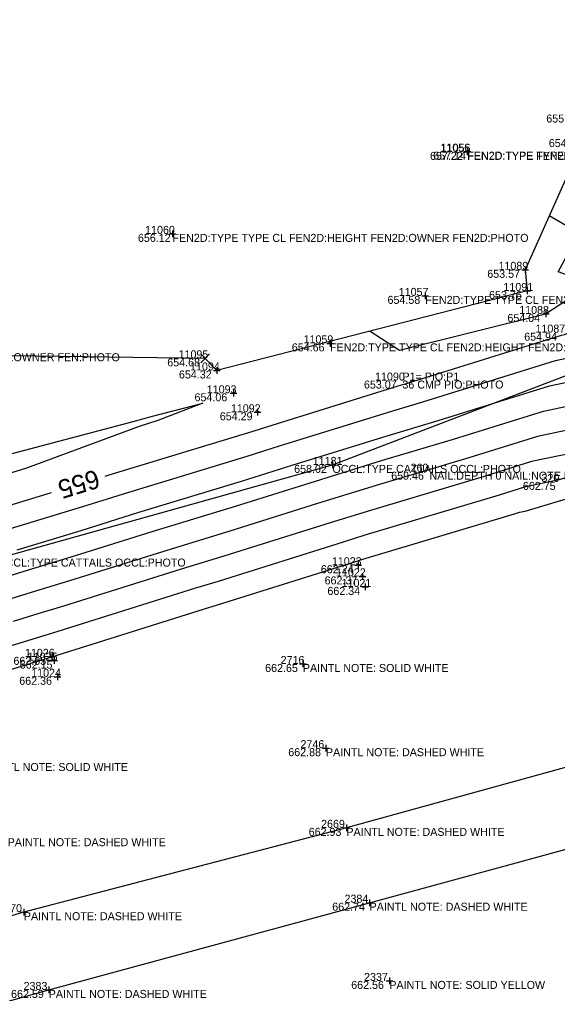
# Model space of a CAD drawing. Extents: x 2129350 to 2137777, y 657588 to 659885.
# Drawn here: x 2130756.2 to 2130836.8, y 658076.4 to 658224.7 of the extents above; entities that cross this region are included whole.
import ezdxf

# ---------------------------------------------------------------- set-up
doc = ezdxf.new("R2010")
doc.units = 0
for name, color, linetype in [('DT_X_Contour_Major', 7, 'Continuous'), ('DT_X_Contour_Minor', 7, 'Continuous'), ('DT_X_TIN_Hull', 7, 'Continuous'), ('PV_X_COP', 7, 'Continuous'), ('SV_X_Occupation_Line', 7, 'Continuous'), ('SV_X_Random_Point', 7, 'Continuous'), ('SV_X_Shot_Marker', 7, 'Continuous'), ('SV_X_Text_Comment', 7, 'Continuous'), ('SV_X_Text_Description', 7, 'Continuous'), ('SV_X_Text_Elevation', 7, 'Continuous'), ('SV_X_Text_Name', 7, 'Continuous')]:
    doc.layers.add(name, color=color, linetype=linetype)

msp = doc.modelspace()

# ---------------------------------------------------------------- linework, layer by layer
at = {"layer": 'DT_X_Contour_Major'}
for points in [[(2130769, 658156.26), (2130769.58, 658156.44), (2130791.18, 658163.02), (2130793.26, 658163.67), (2130812.96, 658169.8), (2130814.34, 658170.21), (2130837.42, 658177.4), (2130837.9, 658177.5), (2130840.51, 658178.62), (2130849.64, 658182.56), (2130850.27, 658181.85), (2130853.26, 658182.7), (2130853.32, 658182.71), (2130854.15, 658182.95), (2130863.79, 658186.07)], [(2130850.97, 658163.03), (2130841.73, 658160.27), (2130832.92, 658158.43), (2130825.82, 658156.21), (2130808.79, 658151.11), (2130802.76, 658149.24), (2130786.79, 658144.23), (2130780.39, 658142.28), (2130762.77, 658136.75), (2130758.92, 658135.58), (2130755.18, 658134.43)], [(2130665.16, 658125.16), (2130676.26, 658128.6), (2130678.88, 658129.42), (2130700.32, 658136.06), (2130702.73, 658136.81), (2130705.65, 658137.65), (2130705.74, 658137.68), (2130727.31, 658143.89), (2130729.75, 658144.64), (2130751.29, 658150.84), (2130753.76, 658151.6), (2130760.97, 658153.79)]]:
    msp.add_lwpolyline(points, dxfattribs=at)
at = {"layer": 'DT_X_Contour_Minor'}
for points in [[(2130754.79, 658148.39), (2130766.3, 658151.9), (2130771.74, 658153.61), (2130790.3, 658159.26), (2130795.16, 658160.78), (2130812.13, 658166.06), (2130816.64, 658167.41), (2130836.52, 658173.61), (2130841.89, 658174.73), (2130849.93, 658178.19), (2130850.42, 658177.65), (2130852.48, 658178.29), (2130857.23, 658180.3), (2130877.62, 658186.9), (2130882.04, 658188.3), (2130901.14, 658194.47), (2130906.8, 658196.25), (2130921.67, 658201.34), (2130941.07, 658207.98)], [(2130755.82, 658145.19), (2130765.42, 658148.11), (2130773.9, 658150.78), (2130789.42, 658155.5), (2130797.06, 658157.9), (2130811.29, 658162.32), (2130818.93, 658164.61), (2130835.62, 658169.81), (2130845.87, 658171.95), (2130850.22, 658173.83), (2130850.49, 658173.53), (2130851.61, 658173.88), (2130861.19, 658177.94), (2130878.35, 658183.5), (2130885.75, 658185.83), (2130901.87, 658191.04), (2130910.36, 658193.7), (2130922.91, 658198), (2130939.29, 658203.61)], [(2130745.25, 658138.41), (2130756.85, 658141.99), (2130764.53, 658144.33), (2130776.06, 658147.94), (2130788.55, 658151.75), (2130798.96, 658155.01), (2130810.46, 658158.59), (2130821.23, 658161.81), (2130834.72, 658166.02), (2130849.85, 658169.18), (2130850.52, 658169.47), (2130850.56, 658169.42), (2130850.73, 658169.47), (2130865.14, 658175.58), (2130879.08, 658180.09), (2130889.46, 658183.36), (2130902.59, 658187.6), (2130913.92, 658191.16), (2130924.16, 658194.66), (2130937.51, 658199.24)], [(2130935.73, 658194.86), (2130925.4, 658191.32), (2130917.48, 658188.61), (2130903.32, 658184.17), (2130893.17, 658180.89), (2130879.81, 658176.69), (2130869.1, 658173.21), (2130856.84, 658168.02), (2130852.13, 658166.55), (2130851.44, 658166.34), (2130846.59, 658164.89), (2130833.82, 658162.22), (2130823.52, 658159.01), (2130809.62, 658154.85), (2130800.86, 658152.13), (2130787.67, 658147.99), (2130778.23, 658145.11), (2130763.65, 658140.54), (2130757.89, 658138.78), (2130743.23, 658134.27)], [(2130808.74, 658178), (2130813.12, 658175.14), (2130835.06, 658180.62), (2130841.92, 658185.12), (2130836.95, 658186.89), (2130838.56, 658189.84), (2130838.43, 658193.64), (2130835.58, 658195.28)], [(2130951.69, 658192.24), (2130932.17, 658186.11), (2130927.89, 658184.65), (2130924.6, 658183.52), (2130904.76, 658177.3), (2130900.58, 658175.95), (2130881.28, 658169.87), (2130877.01, 658168.49), (2130872.12, 658166.42), (2130855.95, 658161.35), (2130853.57, 658160.64), (2130836.87, 658155.65), (2130832.02, 658154.63), (2130828.11, 658153.41), (2130807.96, 658147.38), (2130804.67, 658146.36), (2130785.92, 658140.47), (2130782.55, 658139.45), (2130761.88, 658132.96), (2130759.95, 658132.37), (2130739.21, 658125.98)], [(2130737.2, 658121.84), (2130760.98, 658129.17), (2130761, 658129.17), (2130784.71, 658136.61), (2130785.04, 658136.72), (2130806.57, 658143.47), (2130807.12, 658143.64), (2130830.41, 658150.61), (2130831.12, 658150.84), (2130832.01, 658151.02), (2130854.63, 658157.79), (2130857.85, 658158.75), (2130879.76, 658165.62), (2130880.96, 658166.13), (2130882.01, 658166.47), (2130904.29, 658173.48), (2130905.49, 658173.87)], [(2130750.27, 658158.33), (2130755.24, 658159.68), (2130773.19, 658164.44), (2130776.11, 658165.23), (2130783.64, 658167.21), (2130776.89, 658164.59), (2130774.09, 658163.69), (2130757.18, 658157.47), (2130751.87, 658155.8), (2130750.22, 658155.36), (2130741.58, 658152.89), (2130725.21, 658148.64), (2130722.4, 658147.84), (2130716.87, 658146.48), (2130723.46, 658148.64), (2130724.74, 658149.14), (2130742.63, 658155.2), (2130748.82, 658157.81), (2130750.27, 658158.33)]]:
    msp.add_lwpolyline(points, dxfattribs=at)
at = {"layer": 'DT_X_TIN_Hull'}
msp.add_lwpolyline([(2131077.82, 658286.1), (2131030.27, 658271.69), (2130978.67, 658255.2), (2130938.56, 658242.02), (2130879.71, 658222.62), (2130840.78, 658210.48), (2130840.73, 658206.81), (2130831.97, 658187.2), (2130832.29, 658184.03), (2130785.72, 658172.1), (2130783.99, 658173.92), (2130725.99, 658174.69)], dxfattribs=at)
at = {"layer": 'PV_X_COP'}
for points in [[(2131528.03, 658302.66), (2131480.18, 658289.6), (2131431.72, 658276.11), (2131383.73, 658262.83), (2131335.06, 658249.37), (2131287.25, 658236.79), (2131239.47, 658222.35), (2131190.92, 658209.79), (2131142.98, 658196.28), (2131095.12, 658183.57), (2131046.58, 658169.5), (2130997.83, 658156.5), (2130949.67, 658143.39), (2130901.29, 658130.24), (2130853.81, 658116.91), (2130805.18, 658103.5), (2130756.8, 658090.85), (2130709.64, 658077.1)], [(2130712.28, 658065.72), (2130760.53, 658079.19), (2130808.66, 658092.27), (2130856.27, 658105.25), (2130904.86, 658118.78), (2130952.88, 658132.43), (2131001.46, 658145.23), (2131048.98, 658158.95), (2131098.01, 658172.31), (2131145.3, 658185.44), (2131194.12, 658198.4), (2131242.1, 658211.21), (2131290.4, 658225.02), (2131338.4, 658238.17), (2131386.52, 658251.36), (2131434.96, 658264.62), (2131482.99, 658278.86)]]:
    msp.add_lwpolyline(points, dxfattribs=at)
at = {"layer": 'SV_X_Occupation_Line'}
msp.add_lwpolyline([(2130087.44, 657957.79), (2130125.12, 657969.49), (2130169.35, 657981.55), (2130211.47, 657989.69), (2130262.21, 658002.55), (2130300.39, 658019.48), (2130344.82, 658026.09), (2130388.98, 658037.78), (2130435.6, 658050.49), (2130554.92, 658087.06), (2130644.25, 658113.16), (2130752.81, 658143.9), (2130803.09, 658157.94), (2130847.96, 658175.12), (2130903.78, 658194.81)], dxfattribs=at)
at = {"layer": 'SV_X_Random_Point'}
for p, q in [((2130783.33, 658173.26), (2130784.66, 658174.59)), ((2130783.33, 658174.59), (2130784.66, 658173.26))]:
    msp.add_line(p, q, dxfattribs=at)
at = {"layer": 'SV_X_Shot_Marker'}
for p, q in [((2130822.81, 658204.89), (2130823.81, 658204.89)), ((2130822.83, 658204.93), (2130823.83, 658204.93)), ((2130823.31, 658205.39), (2130823.31, 658204.39)), ((2130823.31, 658204.89), (2130823.31, 658204.89)), ((2130823.33, 658205.43), (2130823.33, 658204.43)), ((2130823.33, 658204.93), (2130823.33, 658204.93)), ((2130778.59, 658192.59), (2130779.59, 658192.59)), ((2130779.09, 658193.09), (2130779.09, 658192.09)), ((2130779.09, 658192.59), (2130779.09, 658192.59)), ((2130831.47, 658187.2), (2130832.47, 658187.2)), ((2130831.97, 658187.7), (2130831.97, 658186.7)), ((2130831.97, 658187.2), (2130831.97, 658187.2)), ((2130817.01, 658183.79), (2130817.01, 658182.79)), ((2130831.79, 658184.03), (2130832.79, 658184.03)), ((2130832.29, 658184.53), (2130832.29, 658183.53)), ((2130832.29, 658184.03), (2130832.29, 658184.03)), ((2130816.51, 658183.29), (2130817.51, 658183.29)), ((2130817.01, 658183.29), (2130817.01, 658183.29)), ((2130834.59, 658180.58), (2130835.59, 658180.58)), ((2130835.09, 658181.08), (2130835.09, 658180.08)), ((2130835.09, 658180.58), (2130835.09, 658180.58)), ((2130802.23, 658176.17), (2130803.23, 658176.17)), ((2130802.73, 658176.67), (2130802.73, 658175.67)), ((2130802.73, 658176.17), (2130802.73, 658176.17)), ((2130785.22, 658172.1), (2130786.22, 658172.1)), ((2130785.72, 658172.6), (2130785.72, 658171.6)), ((2130785.72, 658172.1), (2130785.72, 658172.1)), ((2130787.74, 658168.68), (2130788.74, 658168.68)), ((2130788.24, 658169.18), (2130788.24, 658168.18)), ((2130788.24, 658168.68), (2130788.24, 658168.68)), ((2130791.33, 658165.83), (2130792.33, 658165.83)), ((2130791.83, 658166.33), (2130791.83, 658165.33)), ((2130791.83, 658165.83), (2130791.83, 658165.83)), ((2130803.09, 658158.44), (2130803.09, 658157.44)), ((2130802.59, 658157.94), (2130803.59, 658157.94)), ((2130803.09, 658157.94), (2130803.09, 658157.94)), ((2130806.46, 658142.89), (2130807.46, 658142.89)), ((2130806.96, 658143.39), (2130806.96, 658142.39)), ((2130806.96, 658142.89), (2130806.96, 658142.89)), ((2130807.07, 658141.22), (2130808.07, 658141.22)), ((2130807.57, 658141.72), (2130807.57, 658140.72)), ((2130807.57, 658141.22), (2130807.57, 658141.22)), ((2130807.48, 658139.64), (2130808.48, 658139.64)), ((2130807.98, 658140.14), (2130807.98, 658139.14)), ((2130807.98, 658139.64), (2130807.98, 658139.64)), ((2130760.49, 658129.15), (2130761.49, 658129.15)), ((2130760.99, 658129.65), (2130760.99, 658128.65)), ((2130760.99, 658129.15), (2130760.99, 658129.15)), ((2130761.35, 658129.08), (2130761.35, 658128.08)), ((2130760.85, 658128.58), (2130761.85, 658128.58)), ((2130761.35, 658128.58), (2130761.35, 658128.58)), ((2130798.15, 658128.08), (2130799.15, 658128.08)), ((2130798.65, 658128.58), (2130798.65, 658127.58)), ((2130798.65, 658128.08), (2130798.65, 658128.08)), ((2130761.35, 658126.16), (2130762.35, 658126.16)), ((2130761.85, 658126.66), (2130761.85, 658125.66)), ((2130761.85, 658126.16), (2130761.85, 658126.16)), ((2130801.61, 658115.45), (2130802.61, 658115.45)), ((2130802.11, 658115.95), (2130802.11, 658114.95)), ((2130802.11, 658115.45), (2130802.11, 658115.45)), ((2130804.68, 658103.5), (2130805.68, 658103.5)), ((2130805.18, 658104), (2130805.18, 658103)), ((2130805.18, 658103.5), (2130805.18, 658103.5)), ((2130808.16, 658092.27), (2130809.16, 658092.27)), ((2130808.66, 658092.77), (2130808.66, 658091.77)), ((2130808.66, 658092.27), (2130808.66, 658092.27)), ((2130756.3, 658090.85), (2130757.3, 658090.85)), ((2130756.8, 658091.35), (2130756.8, 658090.35)), ((2130756.8, 658090.85), (2130756.8, 658090.85)), ((2130811.12, 658080.54), (2130812.12, 658080.54)), ((2130811.62, 658081.04), (2130811.62, 658080.04)), ((2130811.62, 658080.54), (2130811.62, 658080.54)), ((2130760.03, 658079.19), (2130761.03, 658079.19)), ((2130760.53, 658079.69), (2130760.53, 658078.69)), ((2130760.53, 658079.19), (2130760.53, 658079.19))]:
    msp.add_line(p, q, dxfattribs=at)

# ---------------------------------------------------------------- texts
at = {"layer": 'DT_X_Contour_Major'}
msp.add_text('655', height=2.8, rotation=197.0498, dxfattribs=at).set_placement((2130767.64, 658157.3))
at = {"layer": 'SV_X_Text_Comment'}
for s, p in [('FEN2D:TYPE FEN2D:HEIGHT FEN2D:OWNER FEN2D:PHOTO', (2130823.31, 658203.69)), ('FEN2D:TYPE TYPE CL FEN2D:HEIGHT FEN2D:OWNER FEN2D:PHOTO', (2130823.33, 658203.73)), ('FEN2D:TYPE TYPE CL FEN2D:HEIGHT FEN2D:OWNER FEN2D:PHOTO', (2130779.09, 658191.39)), ('FEN2D:TYPE TYPE CL FEN2D:HEIGHT FEN2D:OWNER FEN2D:PHOTO', (2130817.01, 658182.09)), ('FEN2D:TYPE TYPE CL FEN2D:HEIGHT FEN2D:OWNER FEN2D:PHOTO', (2130802.73, 658174.97)), ('FEN:TYPE TYPE CL FEN:HEIGHT FEN:OWNER FEN:PHOTO', (2130726, 658173.49)), ('36 CMP PIO:PHOTO', (2130813.58, 658169.39)), ('OCCL:TYPE CATTAILS OCCL:PHOTO', (2130803.09, 658156.74)), ('NAIL:DEPTH 0 NAIL:NOTE NAIL:PHOTO', (2130817.64, 658155.72)), ('OCCL:TYPE CATTAILS OCCL:PHOTO', (2130752.81, 658142.69)), ('PAINTL NOTE: SOLID WHITE', (2130798.65, 658126.88)), ('PAINTL NOTE: DASHED WHITE', (2130802.11, 658114.25)), ('PAINTL NOTE: SOLID WHITE', (2130750.56, 658112.03)), ('PAINTL NOTE: DASHED WHITE', (2130805.18, 658102.3)), ('PAINTL NOTE: DASHED WHITE', (2130754.37, 658100.75)), ('PAINTL NOTE: DASHED WHITE', (2130808.66, 658091.07)), ('PAINTL NOTE: DASHED WHITE', (2130756.8, 658089.65)), ('PAINTL NOTE: SOLID YELLOW', (2130811.62, 658079.34)), ('PAINTL NOTE: DASHED WHITE', (2130760.53, 658077.99))]:
    msp.add_text(s, height=1.2, dxfattribs=at).set_placement(p)
at = {"layer": 'SV_X_Text_Description'}
msp.add_text('P1= PIO:P1', height=1.2, dxfattribs=at).set_placement((2130813.58, 658170.59))
at = {"layer": 'SV_X_Text_Elevation'}
for s, p in [('655.25', (2130835.16, 658209.29)), ('654.71', (2130835.54, 658205.61)), ('657.22', (2130817.72, 658203.69)), ('657.14', (2130818.2, 658203.73)), ('656.12', (2130773.91, 658191.39)), ('653.57', (2130826.31, 658186)), ('653.76', (2130826.58, 658182.83)), ('654.58', (2130811.35, 658182.09)), ('654.04', (2130829.33, 658179.38)), ('654.94', (2130831.85, 658176.57)), ('654.66', (2130796.99, 658174.97)), ('654.68', (2130778.31, 658172.72)), ('654.32', (2130780.06, 658170.9)), ('653.07', (2130807.81, 658169.39)), ('654.06', (2130782.4, 658167.48)), ('654.29', (2130786.19, 658164.63)), ('658.02', (2130797.34, 658156.74)), ('659.46', (2130811.9, 658155.72)), ('662.75', (2130831.65, 658154.19)), ('662.24', (2130801.34, 658141.69)), ('662.37', (2130801.91, 658140.02)), ('662.34', (2130802.33, 658138.44)), ('662.05', (2130755.24, 658127.95)), ('662.15', (2130756.18, 658127.38)), ('662.65', (2130792.99, 658126.88)), ('662.36', (2130756.11, 658124.96)), ('662.88', (2130796.46, 658114.25)), ('662.93', (2130799.52, 658102.3)), ('662.74', (2130803.05, 658091.07)), ('662.56', (2130805.9, 658079.34)), ('662.59', (2130754.88, 658077.99))]:
    msp.add_text(s, height=1.2, dxfattribs=at).set_placement(p)
at = {"layer": 'SV_X_Text_Name'}
for s, p in [('11056', (2130819.28, 658204.93)), ('11055', (2130819.34, 658204.89)), ('11060', (2130774.99, 658192.59)), ('11089', (2130827.99, 658187.2)), ('11091', (2130828.73, 658184.03)), ('11057', (2130813.03, 658183.29)), ('11088', (2130831.1, 658180.58)), ('11087', (2130833.54, 658177.78)), ('11059', (2130798.75, 658176.17)), ('11095', (2130780, 658173.92)), ('11094', (2130781.73, 658172.1)), ('11090', (2130809.48, 658170.59)), ('11093', (2130784.24, 658168.68)), ('11092', (2130787.85, 658165.83)), ('11181', (2130800.13, 658157.94)), ('260', (2130814.81, 658156.92)), ('320', (2130834.44, 658155.39)), ('11023', (2130803, 658142.89)), ('11022', (2130803.62, 658141.22)), ('11021', (2130804.46, 658139.64)), ('11026', (2130756.96, 658129.15)), ('11025', (2130757.39, 658128.58)), ('2716', (2130795.32, 658128.08)), ('11024', (2130757.9, 658126.16)), ('2746', (2130798.29, 658115.45)), ('2669', (2130801.38, 658103.5)), ('2384', (2130804.9, 658092.27)), ('2670', (2130752.95, 658090.85)), ('2337', (2130807.83, 658080.54)), ('2383', (2130756.76, 658079.19))]:
    msp.add_text(s, height=1.2, dxfattribs=at).set_placement(p)

doc.saveas('drawing.dxf')
